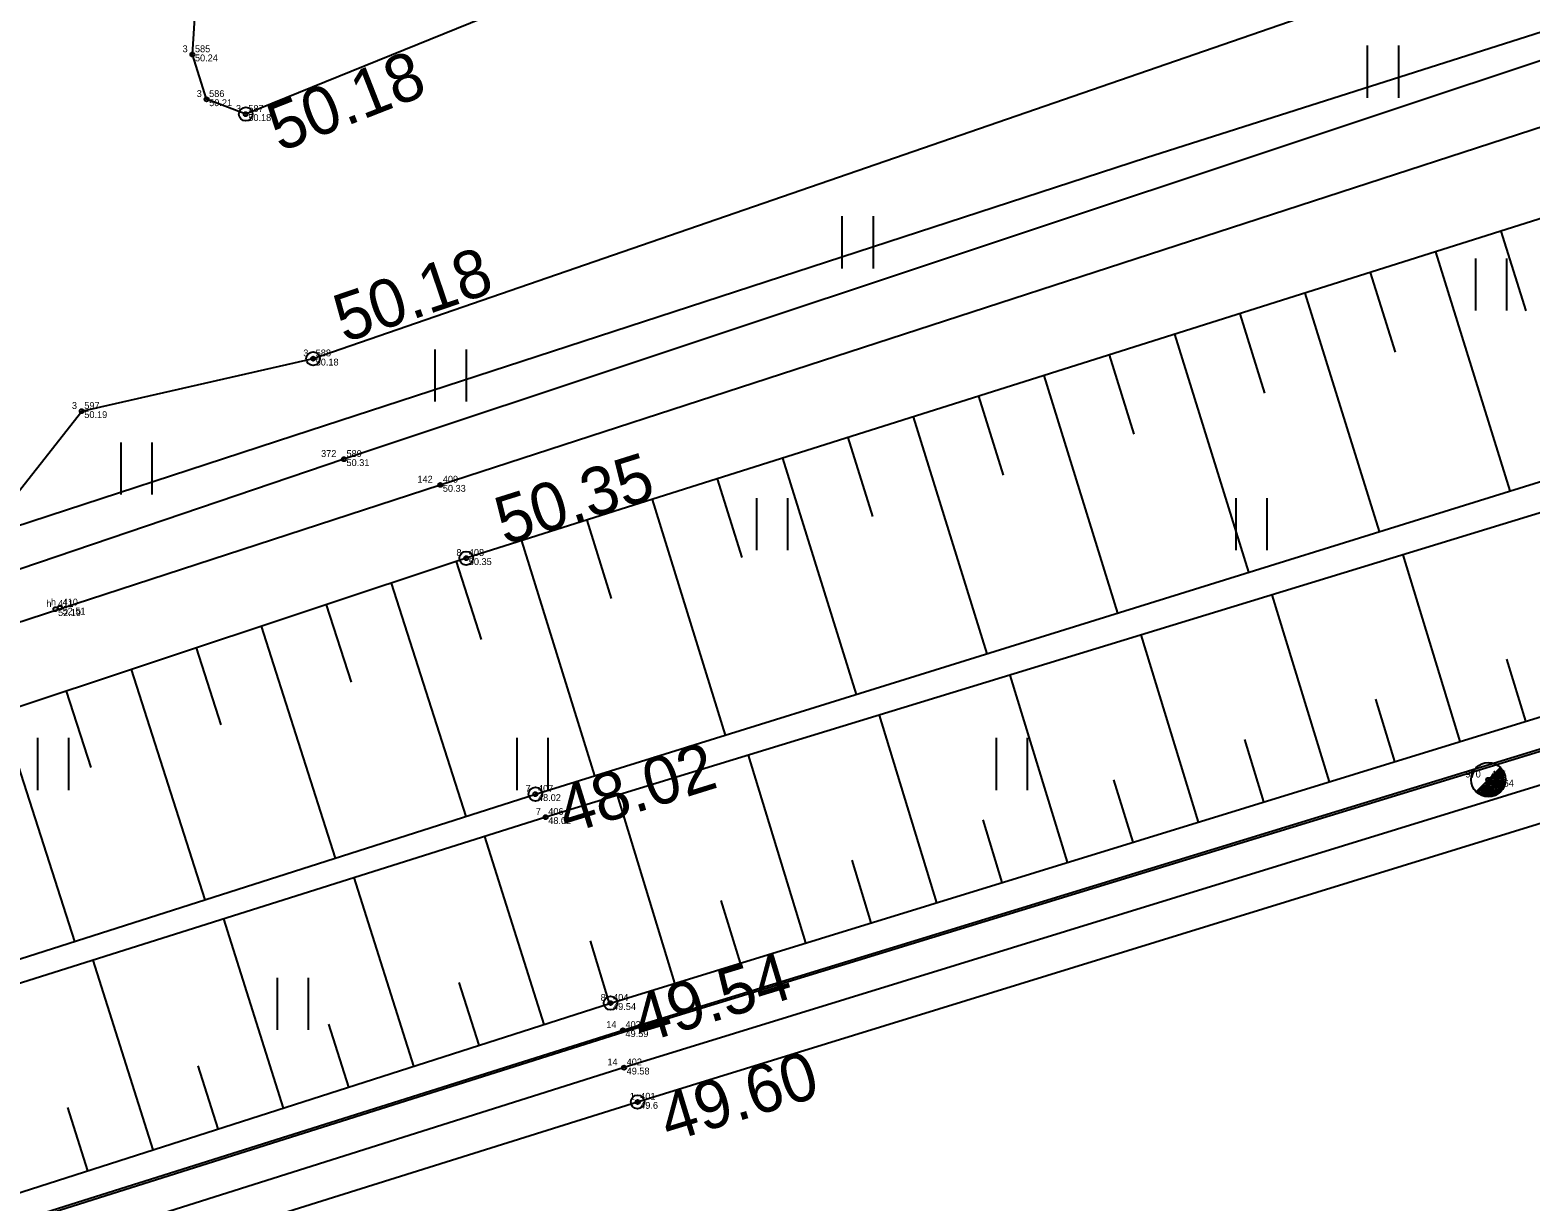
# Model space of a CAD drawing. Extents: x 543497 to 552146, y 6567125 to 6579845.
# Drawn here: x 546062.67 to 546084.57, y 6577690.61 to 6577707.71 of the extents above; entities that cross this region are included whole.
import ezdxf

# ---------------------------------------------------------------- set-up
doc = ezdxf.new("R2010")
doc.units = 0
for name, color, linetype in [('xref_Kangru tee 1_geodeesia$0$AED', 7, 'Continuous'), ('xref_Kangru tee 1_geodeesia$0$HALJASTUS', 7, 'Continuous'), ('xref_Kangru tee 1_geodeesia$0$korgus-EH2000', 7, 'Continuous'), ('xref_Kangru tee 1_geodeesia$0$Liiklus', 7, 'Continuous'), ('xref_Kangru tee 1_geodeesia$0$mootkood', 7, 'Continuous'), ('xref_Kangru tee 1_geodeesia$0$MOOTKORG-eh2000', 7, 'Continuous'), ('xref_Kangru tee 1_geodeesia$0$mootmpunkt', 7, 'Continuous'), ('xref_Kangru tee 1_geodeesia$0$MOOTNR', 7, 'Continuous'), ('xref_Kangru tee 1_geodeesia$0$Post', 7, 'Continuous'), ('xref_Kangru tee 1_geodeesia$0$PUU', 7, 'Continuous'), ('xref_Kangru tee 1_geodeesia$0$RELJEEF', 7, 'Continuous'), ('xref_Kangru tee 1_geodeesia$0$SITRASS', 7, 'Continuous'), ('xref_Kangru tee 1_geodeesia$0$TEE', 7, 'Continuous')]:
    doc.layers.add(name, color=color, linetype=linetype)

# ---------------------------------------------------------------- blocks, each defined once
blk = doc.blocks.new('xref_Kangru tee 1_geodeesia$0$plpost')
blk.add_line((-0.354, -0.353), (0.353, 0.354))
blk.add_circle((0, 0), 0.5)
for radius, start, end in [(0.45, 224.8541, 45.0356), (0.4, 224.8427, 45.047), (0.35, 224.8281, 45.0616), (0.3, 224.8087, 45.081), (0.25, 224.7814, 45.1083), (0.2, 224.7406, 45.1491), (0.15, 224.6725, 45.2172), (0.1, 224.5363, 45.3534), (0.05, 224.1278, 45.7619)]:
    blk.add_arc((0, 0), radius, start, end)
blk = doc.blocks.new('xref_Kangru tee 1_geodeesia$0$hein')
for p, q in [((-0.455, 0.761), (-0.455, -0.761)), ((0.455, 0.761), (0.455, -0.761))]:
    blk.add_line(p, q)

msp = doc.modelspace()

# ---------------------------------------------------------------- linework, layer by layer
at = {"layer": 'xref_Kangru tee 1_geodeesia$0$AED'}
msp.add_lwpolyline([(545979.768, 6577672.182), (545997.507, 6577677.911), (546020.844, 6577685.508), (546045.969, 6577693.685), (546068.657, 6577701.074), (546085.99, 6577706.708), (546091.783, 6577708.468), (546114.483, 6577715.305), (546122.781, 6577717.859)], dxfattribs=at)
at = {"layer": 'xref_Kangru tee 1_geodeesia$0$korgus-EH2000'}
for centre in [(546065.816, 6577706.486), (546066.8, 6577702.917), (546069.036, 6577700.004), (546070.046, 6577696.56), (546071.143, 6577693.51), (546071.539, 6577692.067)]:
    msp.add_circle(centre, 0.1, dxfattribs=at)
at = {"layer": 'xref_Kangru tee 1_geodeesia$0$Liiklus'}
for points in [[(546140.1, 6577713.825), (546117.037, 6577707.038), (546094.195, 6577700.083), (546071.336, 6577693.084), (546048.1, 6577685.746), (546023.804, 6577677.834), (545999.945, 6577669.953), (545974.62, 6577661.424), (545953.584, 6577654.176), (545929.781, 6577645.689), (545906.69, 6577637.378)], [(546140.387, 6577713.403), (546116.908, 6577706.504), (546094.508, 6577699.709), (546071.341, 6577692.568), (546048.377, 6577685.322), (546024.051, 6577677.467), (546000.007, 6577669.497), (545974.577, 6577660.93), (545953.828, 6577653.707), (545929.813, 6577645.16), (545906.85, 6577636.866)]]:
    msp.add_lwpolyline(points, dxfattribs=at)
at = {"layer": 'xref_Kangru tee 1_geodeesia$0$mootmpunkt'}
for centre in [(546065.037, 6577707.357), (546065.244, 6577706.703), (546065.816, 6577706.486), (546066.8, 6577702.917), (546063.421, 6577702.15), (546067.25, 6577701.449), (546068.657, 6577701.074), (546069.036, 6577700.004), (546063.038, 6577699.261), (546063.104, 6577699.281), (546070.046, 6577696.56), (546083.962, 6577696.77), (546070.196, 6577696.224), (546071.143, 6577693.51), (546071.324, 6577693.114), (546071.341, 6577692.568), (546071.539, 6577692.067)]:
    msp.add_circle(centre, 0.03, dxfattribs=at)
at = {"layer": 'xref_Kangru tee 1_geodeesia$0$PUU'}
msp.add_lwpolyline([(546117.866, 6577717.426), (546113.699, 6577716.286), (546090.767, 6577709.285), (546067.25, 6577701.449), (546060.951, 6577699.314), (546047.057, 6577695.034), (546019.897, 6577686.031), (545997.772, 6577678.867)], dxfattribs=at)
at = {"layer": 'xref_Kangru tee 1_geodeesia$0$RELJEEF'}
for p, q in [((546084.145, 6577704.779), (546084.507, 6577703.614)), ((546083.191, 6577704.478), (546084.277, 6577700.986)), ((546082.238, 6577704.176), (546082.599, 6577703.014)), ((546081.284, 6577703.875), (546082.367, 6577700.392)), ((546080.331, 6577703.573), (546080.691, 6577702.414)), ((546079.377, 6577703.272), (546080.458, 6577699.798)), ((546078.424, 6577702.971), (546078.783, 6577701.814)), ((546077.47, 6577702.669), (546078.548, 6577699.204)), ((546076.517, 6577702.368), (546076.875, 6577701.215)), ((546075.563, 6577702.067), (546076.638, 6577698.61)), ((546074.61, 6577701.765), (546074.967, 6577700.615)), ((546073.656, 6577701.464), (546074.728, 6577698.016)), ((546072.702, 6577701.163), (546073.06, 6577700.015)), ((546071.749, 6577700.861), (546072.819, 6577697.422)), ((546070.795, 6577700.56), (546071.152, 6577699.415)), ((546069.842, 6577700.259), (546070.909, 6577696.828)), ((546068.889, 6577699.955), (546069.253, 6577698.817)), ((546083.552, 6577697.33), (546082.719, 6577700.054)), ((546067.94, 6577699.64), (546069.028, 6577696.235)), ((546081.641, 6577696.742), (546080.806, 6577699.469)), ((546066.991, 6577699.325), (546067.353, 6577698.193)), ((546066.042, 6577699.01), (546067.123, 6577695.626)), ((546079.729, 6577696.153), (546078.894, 6577698.884)), ((546065.093, 6577698.694), (546065.452, 6577697.57)), ((546064.144, 6577698.379), (546065.218, 6577695.017)), ((546084.508, 6577697.625), (546084.23, 6577698.532)), ((546077.818, 6577695.565), (546076.981, 6577698.299)), ((546063.195, 6577698.064), (546063.552, 6577696.947)), ((546082.596, 6577697.036), (546082.318, 6577697.945)), ((546062.246, 6577697.749), (546063.313, 6577694.409)), ((546075.906, 6577694.976), (546075.069, 6577697.714)), ((546080.685, 6577696.448), (546080.407, 6577697.357)), ((546073.995, 6577694.388), (546073.156, 6577697.129)), ((546078.773, 6577695.859), (546078.495, 6577696.77)), ((546072.083, 6577693.799), (546071.244, 6577696.544)), ((546076.862, 6577695.271), (546076.583, 6577696.183)), ((546070.175, 6577693.2), (546069.308, 6577695.943)), ((546074.95, 6577694.682), (546074.671, 6577695.595)), ((546068.271, 6577692.589), (546067.401, 6577695.341)), ((546073.039, 6577694.094), (546072.759, 6577695.008)), ((546066.366, 6577691.978), (546065.494, 6577694.738)), ((546071.128, 6577693.505), (546070.848, 6577694.421)), ((546064.462, 6577691.367), (546063.587, 6577694.135)), ((546069.223, 6577692.894), (546068.934, 6577693.81)), ((546067.319, 6577692.283), (546067.028, 6577693.202)), ((546065.414, 6577691.673), (546065.123, 6577692.594)), ((546063.51, 6577691.062), (546063.218, 6577691.986))]:
    msp.add_line(p, q, dxfattribs=at)
for points in [[(546137.781, 6577720.873), (546114.77, 6577714.002), (546092.255, 6577707.342), (546069.036, 6577700.004), (546046.331, 6577692.462), (546021.153, 6577684.174), (545998.132, 6577676.3), (545981.547, 6577670.953), (545979.653, 6577670.251), (545977.742, 6577668.092), (545973.561, 6577666.634), (545951.988, 6577659.65), (545928.335, 6577650.688), (545904.994, 6577641.739)], [(545905.098, 6577640.602), (545928.795, 6577649.24), (545952.573, 6577657.509), (545973.845, 6577665.057), (545998.977, 6577673.496), (546022.767, 6577681.409), (546047.252, 6577689.277), (546070.046, 6577696.56), (546093.21, 6577703.765), (546115.551, 6577710.628), (546138.679, 6577717.517)], [(546138.846, 6577717.098), (546115.769, 6577710.175), (546093.427, 6577703.329), (546070.196, 6577696.224), (546047.366, 6577689.009), (546022.94, 6577680.981), (545999.142, 6577673.218), (545974.092, 6577664.733), (545952.67, 6577657.308), (545928.977, 6577648.899), (545905.275, 6577640.335)], [(545906.4, 6577637.514), (545929.723, 6577645.93), (545953.414, 6577654.409), (545974.54, 6577661.798), (545999.874, 6577670.254), (546023.65, 6577678.306), (546048.031, 6577686.097), (546071.143, 6577693.51), (546094, 6577700.547), (546116.929, 6577707.47), (546139.866, 6577714.146)]]:
    msp.add_lwpolyline(points, dxfattribs=at)
at = {"layer": 'xref_Kangru tee 1_geodeesia$0$SITRASS'}
msp.add_lwpolyline([(545908.485, 6577643.705), (545911.194, 6577646.612), (545925.706, 6577656.002), (545927.481, 6577656.734), (545938.042, 6577659.913), (545948.418, 6577663.054), (545958.853, 6577666.457), (545971.932, 6577670.246), (545983.129, 6577674.156), (545994.132, 6577677.914), (546005.032, 6577681.831), (546015.499, 6577685.452), (546025.557, 6577688.556), (546030.559, 6577690.213), (546046.952, 6577695.414), (546066.518, 6577701.793), (546078.972, 6577705.852), (546100.203, 6577712.621), (546110.553, 6577715.537), (546117.41, 6577717.31), (546125.411, 6577719.428), (546136.464, 6577722.314), (546141.561, 6577723.784)], dxfattribs=at)
at = {"layer": 'xref_Kangru tee 1_geodeesia$0$TEE'}
for points in [[(545971.433, 6577672.366), (545997.276, 6577680.49), (546019.075, 6577687.637), (546046.227, 6577696.261), (546050.233, 6577697.38), (546060.833, 6577699.813), (546062.092, 6577700.466), (546063.421, 6577702.15), (546066.8, 6577702.917), (546090.631, 6577711.146), (546112.837, 6577718.304), (546121.35, 6577721.07), (546120.4, 6577725.737), (546111.41, 6577723.208), (546088.914, 6577715.843), (546065.816, 6577706.486), (546065.244, 6577706.703), (546065.037, 6577707.357), (546065.171, 6577709.425), (546065.38, 6577710.653), (546064.96, 6577714.947), (546067.921, 6577716.792), (546070.994, 6577716.678), (546072.733, 6577718.476)], [(545906.85, 6577636.866), (545929.889, 6577645.059), (545953.872, 6577653.571), (545974.605, 6577661.456), (545999.934, 6577669.987), (546023.789, 6577677.871), (546048.093, 6577685.795), (546071.324, 6577693.114), (546094.183, 6577700.122), (546117.024, 6577707.078), (546140.081, 6577713.851)], [(545907.046, 6577636.431), (545930.044, 6577644.691), (545953.99, 6577653.148), (545974.87, 6577660.403), (546000.141, 6577668.988), (546024.289, 6577677), (546048.596, 6577684.894), (546071.539, 6577692.067), (546094.678, 6577699.21), (546117.101, 6577706.011), (546140.733, 6577712.948)]]:
    msp.add_lwpolyline(points, dxfattribs=at)

# ---------------------------------------------------------------- block references
at = {"layer": 'xref_Kangru tee 1_geodeesia$0$HALJASTUS', "xscale": 0.5, "yscale": 0.5}
for p in [(546082.42, 6577707.106), (546074.75, 6577704.614), (546084, 6577704), (546068.806, 6577702.671), (546064.219, 6577701.314), (546073.5, 6577700.5), (546080.5, 6577700.5), (546063, 6577697), (546070, 6577697), (546077, 6577697), (546066.5, 6577693.5)]:
    msp.add_blockref('xref_Kangru tee 1_geodeesia$0$hein', p, dxfattribs=at)
at = {"layer": 'xref_Kangru tee 1_geodeesia$0$Post', "xscale": 0.5, "yscale": 0.5}
msp.add_blockref('xref_Kangru tee 1_geodeesia$0$plpost', (546083.962, 6577696.77), dxfattribs=at)

# ---------------------------------------------------------------- texts
at = {"layer": 'xref_Kangru tee 1_geodeesia$0$korgus-EH2000'}
for s, rotation, p in [(' 50.18 ', 21.4077, (546066.072, 6577705.834)), (' 50.18 ', 18.7791, (546067.008, 6577703.062)), (' 50.35 ', 17.4566, (546069.349, 6577700.113)), (' 48.02 ', 17.3301, (546070.255, 6577695.892)), (' 49.54 ', 16.9132, (546071.347, 6577692.84)), (' 49.60 ', 17.0395, (546071.744, 6577691.398))]:
    msp.add_text(s, height=0.7, rotation=rotation, dxfattribs=at).set_placement(p)
at = {"layer": 'xref_Kangru tee 1_geodeesia$0$mootkood'}
for s, p in [(' 3', (546064.856, 6577707.39)), (' 3', (546065.063, 6577706.736)), (' 3', (546065.635, 6577706.519)), (' 3', (546066.619, 6577702.95)), (' 3', (546063.24, 6577702.183)), (' 372', (546066.879, 6577701.482)), (' 142', (546068.286, 6577701.107)), (' 8', (546068.855, 6577700.037)), (' h', (546062.867, 6577699.294)), (' h', (546062.933, 6577699.314)), (' 970', (546083.591, 6577696.803)), (' 7', (546069.865, 6577696.593)), (' 7', (546070.015, 6577696.257)), (' 8', (546070.962, 6577693.543)), (' 14', (546071.043, 6577693.147)), (' 14', (546071.06, 6577692.601)), (' 1', (546071.387, 6577692.1))]:
    msp.add_text(s, height=0.1, dxfattribs=at).set_placement(p)
at = {"layer": 'xref_Kangru tee 1_geodeesia$0$MOOTKORG-eh2000'}
for s, p in [(' 50.24', (546065.037, 6577707.257)), (' 50.21', (546065.244, 6577706.603)), (' 50.18', (546065.816, 6577706.386)), (' 50.18', (546066.8, 6577702.817)), (' 50.19', (546063.421, 6577702.05)), (' 50.31', (546067.25, 6577701.349)), (' 50.33', (546068.657, 6577700.974)), (' 50.35', (546069.036, 6577699.904)), (' 52.19', (546063.038, 6577699.161)), (' 52.51', (546063.104, 6577699.181)), (' 49.64', (546083.962, 6577696.67)), (' 48.02', (546070.046, 6577696.46)), (' 48.02', (546070.196, 6577696.124)), (' 49.54', (546071.143, 6577693.41)), (' 49.59', (546071.324, 6577693.014)), (' 49.58', (546071.341, 6577692.468)), (' 49.6', (546071.539, 6577691.967))]:
    msp.add_text(s, height=0.1, dxfattribs=at).set_placement(p)
at = {"layer": 'xref_Kangru tee 1_geodeesia$0$MOOTNR'}
for s, p in [(' 585', (546065.037, 6577707.39)), (' 586', (546065.244, 6577706.736)), (' 587', (546065.816, 6577706.519)), (' 588', (546066.8, 6577702.95)), (' 597', (546063.421, 6577702.183)), (' 589', (546067.25, 6577701.482)), (' 409', (546068.657, 6577701.107)), (' 408', (546069.036, 6577700.037)), (' 411', (546063.038, 6577699.294)), (' 410', (546063.104, 6577699.314)), (' 405', (546083.962, 6577696.803)), (' 407', (546070.046, 6577696.593)), (' 406', (546070.196, 6577696.257)), (' 404', (546071.143, 6577693.543)), (' 403', (546071.324, 6577693.147)), (' 402', (546071.341, 6577692.601)), (' 401', (546071.539, 6577692.1))]:
    msp.add_text(s, height=0.1, dxfattribs=at).set_placement(p)

doc.saveas('drawing.dxf')
